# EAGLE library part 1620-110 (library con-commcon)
COMPACT PCI TYPE A - 110 PINS 2mm HARD METRIC SOCKETS
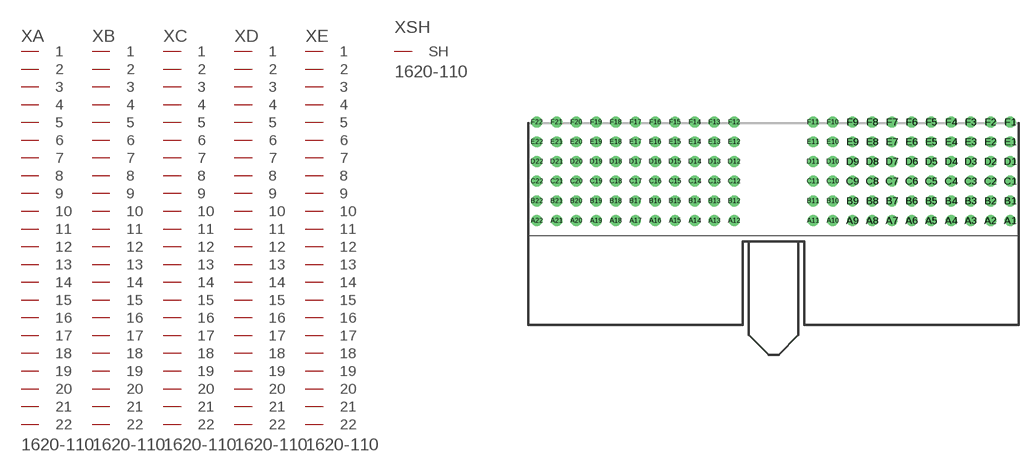
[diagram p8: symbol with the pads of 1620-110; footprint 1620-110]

Designator prefix X; gates A=PIN22 B=PIN22 C=PIN22 D=PIN22 E=PIN22 SH=SHIELD

## 1620-110 (OC_FARNELL: unknown; OC_NEWARK: unknown)  [1620-110]
A1  A:1  pas
A2  A:2  pas
A3  A:3  pas
A4  A:4  pas
A5  A:5  pas
A6  A:6  pas
A7  A:7  pas
A8  A:8  pas
A9  A:9  pas
A10  A:10  pas
A11  A:11  pas
A12  A:12  pas
A13  A:13  pas
A14  A:14  pas
A15  A:15  pas
A16  A:16  pas
A17  A:17  pas
A18  A:18  pas
A19  A:19  pas
A20  A:20  pas
A21  A:21  pas
A22  A:22  pas
B1  B:1  pas
B2  B:2  pas
B3  B:3  pas
B4  B:4  pas
B5  B:5  pas
B6  B:6  pas
B7  B:7  pas
B8  B:8  pas
B9  B:9  pas
B10  B:10  pas
B11  B:11  pas
B12  B:12  pas
B13  B:13  pas
B14  B:14  pas
B15  B:15  pas
B16  B:16  pas
B17  B:17  pas
B18  B:18  pas
B19  B:19  pas
B20  B:20  pas
B21  B:21  pas
B22  B:22  pas
C1  C:1  pas
C2  C:2  pas
C3  C:3  pas
C4  C:4  pas
C5  C:5  pas
C6  C:6  pas
C7  C:7  pas
C8  C:8  pas
C9  C:9  pas
C10  C:10  pas
C11  C:11  pas
C12  C:12  pas
C13  C:13  pas
C14  C:14  pas
C15  C:15  pas
C16  C:16  pas
C17  C:17  pas
C18  C:18  pas
C19  C:19  pas
C20  C:20  pas
C21  C:21  pas
C22  C:22  pas
D1  D:1  pas
D2  D:2  pas
D3  D:3  pas
D4  D:4  pas
D5  D:5  pas
D6  D:6  pas
D7  D:7  pas
D8  D:8  pas
D9  D:9  pas
D10  D:10  pas
D11  D:11  pas
D12  D:12  pas
D13  D:13  pas
D14  D:14  pas
D15  D:15  pas
D16  D:16  pas
D17  D:17  pas
D18  D:18  pas
D19  D:19  pas
D20  D:20  pas
D21  D:21  pas
D22  D:22  pas
E1  E:1  pas
E2  E:2  pas
E3  E:3  pas
E4  E:4  pas
E5  E:5  pas
E6  E:6  pas
E7  E:7  pas
E8  E:8  pas
E9  E:9  pas
E10  E:10  pas
E11  E:11  pas
E12  E:12  pas
E13  E:13  pas
E14  E:14  pas
E15  E:15  pas
E16  E:16  pas
E17  E:17  pas
E18  E:18  pas
E19  E:19  pas
E20  E:20  pas
E21  E:21  pas
E22  E:22  pas
F1  SH:SH  pas

## Footprint 1620-110 (pad centres in mm)
COMPACT PCI TYPE A - 110 PINS 2mm HARD METRIC SOCKETS
drill 0.6 round: A1 24,1.27; A2 22,1.27; A3 20,1.27; A4 18,1.27; A5 16,1.27; A6 14,1.27; A7 12,1.27; A8 10,1.27; A9 8,1.27; A10 6,1.27; A11 4,1.27; A12 -4,1.27; A13 -6,1.27; A14 -8,1.27; A15 -10,1.27; A16 -12,1.27; A17 -14,1.27; A18 -16,1.27; A19 -18,1.27; A20 -20,1.27; A21 -22,1.27; A22 -24,1.27; B1 24,3.27; B2 22,3.27; B3 20,3.27; B4 18,3.27; B5 16,3.27; B6 14,3.27; B7 12,3.27; B8 10,3.27; B9 8,3.27; B10 6,3.27; B11 4,3.27; B12 -4,3.27; B13 -6,3.27; B14 -8,3.27; B15 -10,3.27; B16 -12,3.27; B17 -14,3.27; B18 -16,3.27; B19 -18,3.27; B20 -20,3.27; B21 -22,3.27; B22 -24,3.27; C1 24,5.27; C2 22,5.27; C3 20,5.27; C4 18,5.27; C5 16,5.27; C6 14,5.27; C7 12,5.27; C8 10,5.27; C9 8,5.27; C10 6,5.27; C11 4,5.27; C12 -4,5.27; C13 -6,5.27; C14 -8,5.27; C15 -10,5.27; C16 -12,5.27; C17 -14,5.27; C18 -16,5.27; C19 -18,5.27; C20 -20,5.27; C21 -22,5.27; C22 -24,5.27; D1 24,7.27; D2 22,7.27; D3 20,7.27; D4 18,7.27; D5 16,7.27; D6 14,7.27; D7 12,7.27; D8 10,7.27; D9 8,7.27; D10 6,7.27; D11 4,7.27; D12 -4,7.27; D13 -6,7.27; D14 -8,7.27; D15 -10,7.27; D16 -12,7.27; D17 -14,7.27; D18 -16,7.27; D19 -18,7.27; D20 -20,7.27; D21 -22,7.27; D22 -24,7.27; E1 24,9.27; E2 22,9.27; E3 20,9.27; E4 18,9.27; E5 16,9.27; E6 14,9.27; E7 12,9.27; E8 10,9.27; E9 8,9.27; E10 6,9.27; E11 4,9.27; E12 -4,9.27; E13 -6,9.27; E14 -8,9.27; E15 -10,9.27; E16 -12,9.27; E17 -14,9.27; E18 -16,9.27; E19 -18,9.27; E20 -20,9.27; E21 -22,9.27; E22 -24,9.27; F1 24,11.27; F2 22,11.27; F3 20,11.27; F4 18,11.27; F5 16,11.27; F6 14,11.27; F7 12,11.27; F8 10,11.27; F9 8,11.27; F10 6,11.27; F11 4,11.27; F12 -4,11.27; F13 -6,11.27; F14 -8,11.27; F15 -10,11.27; F16 -12,11.27; F17 -14,11.27; F18 -16,11.27; F19 -18,11.27; F20 -20,11.27; F21 -22,11.27; F22 -24,11.27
